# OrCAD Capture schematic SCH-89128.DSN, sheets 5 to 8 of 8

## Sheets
5 03 POWER: size D
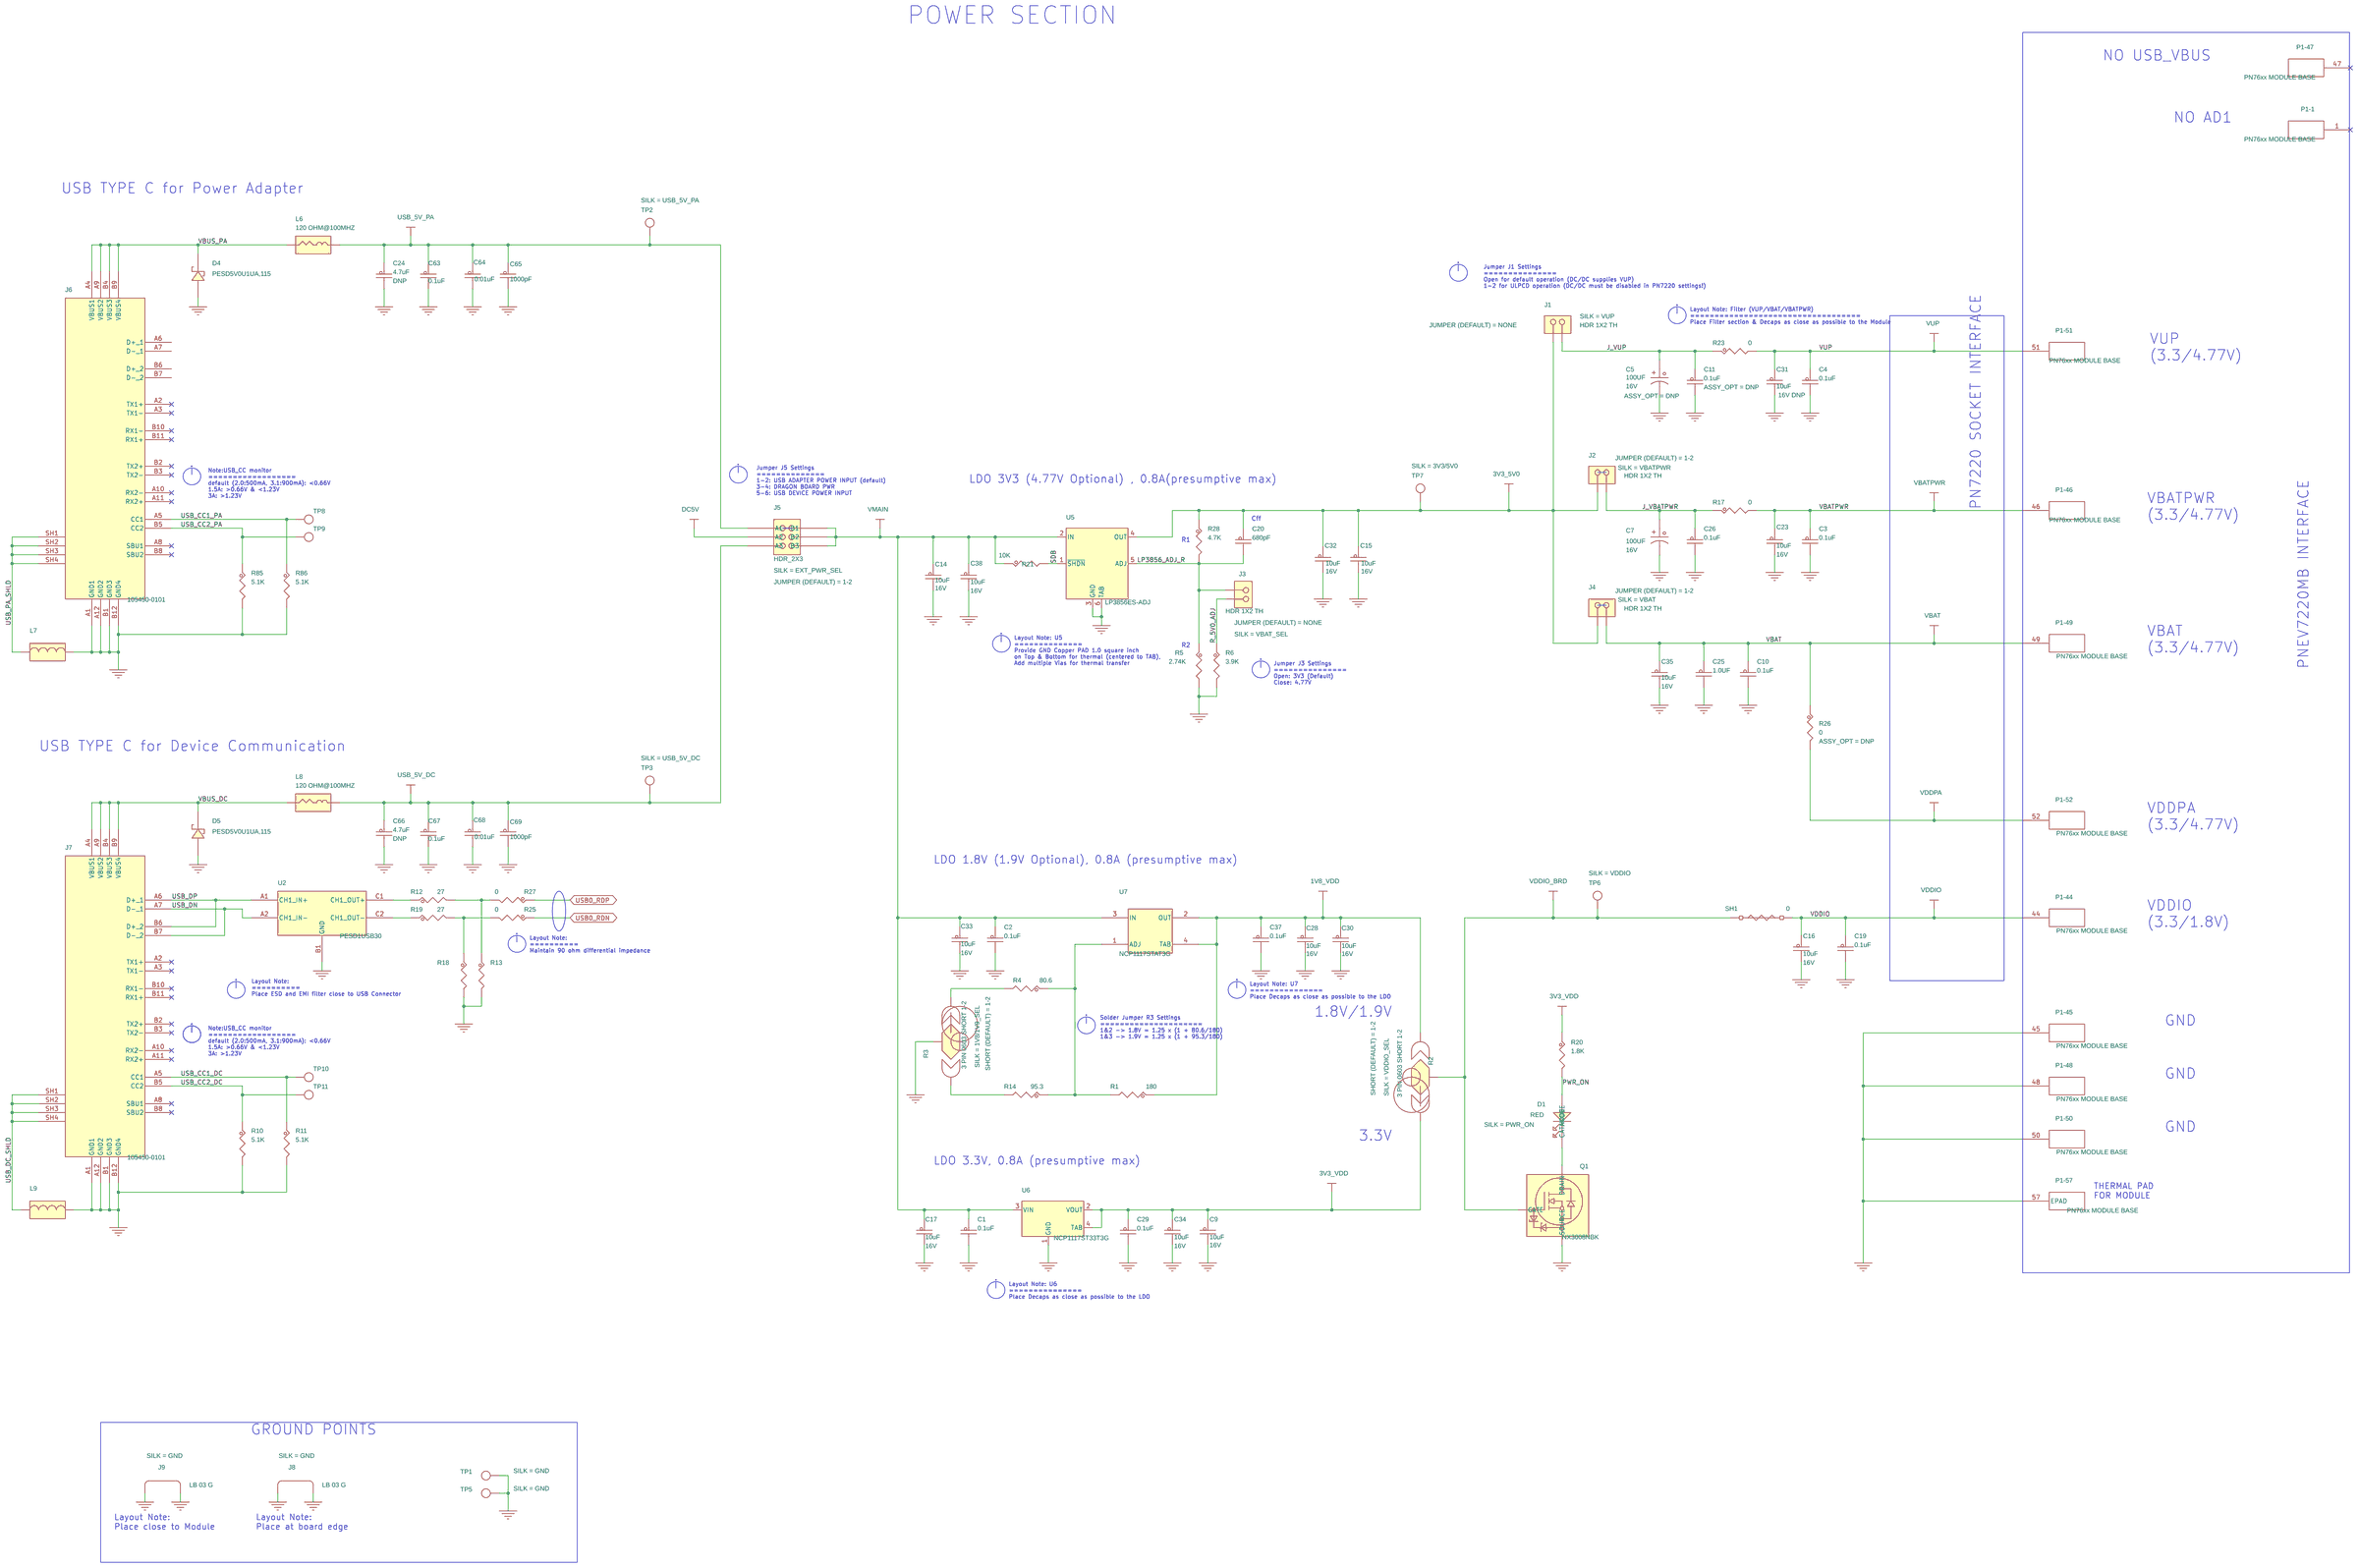
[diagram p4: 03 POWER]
6 04 NFCC Interface: size D
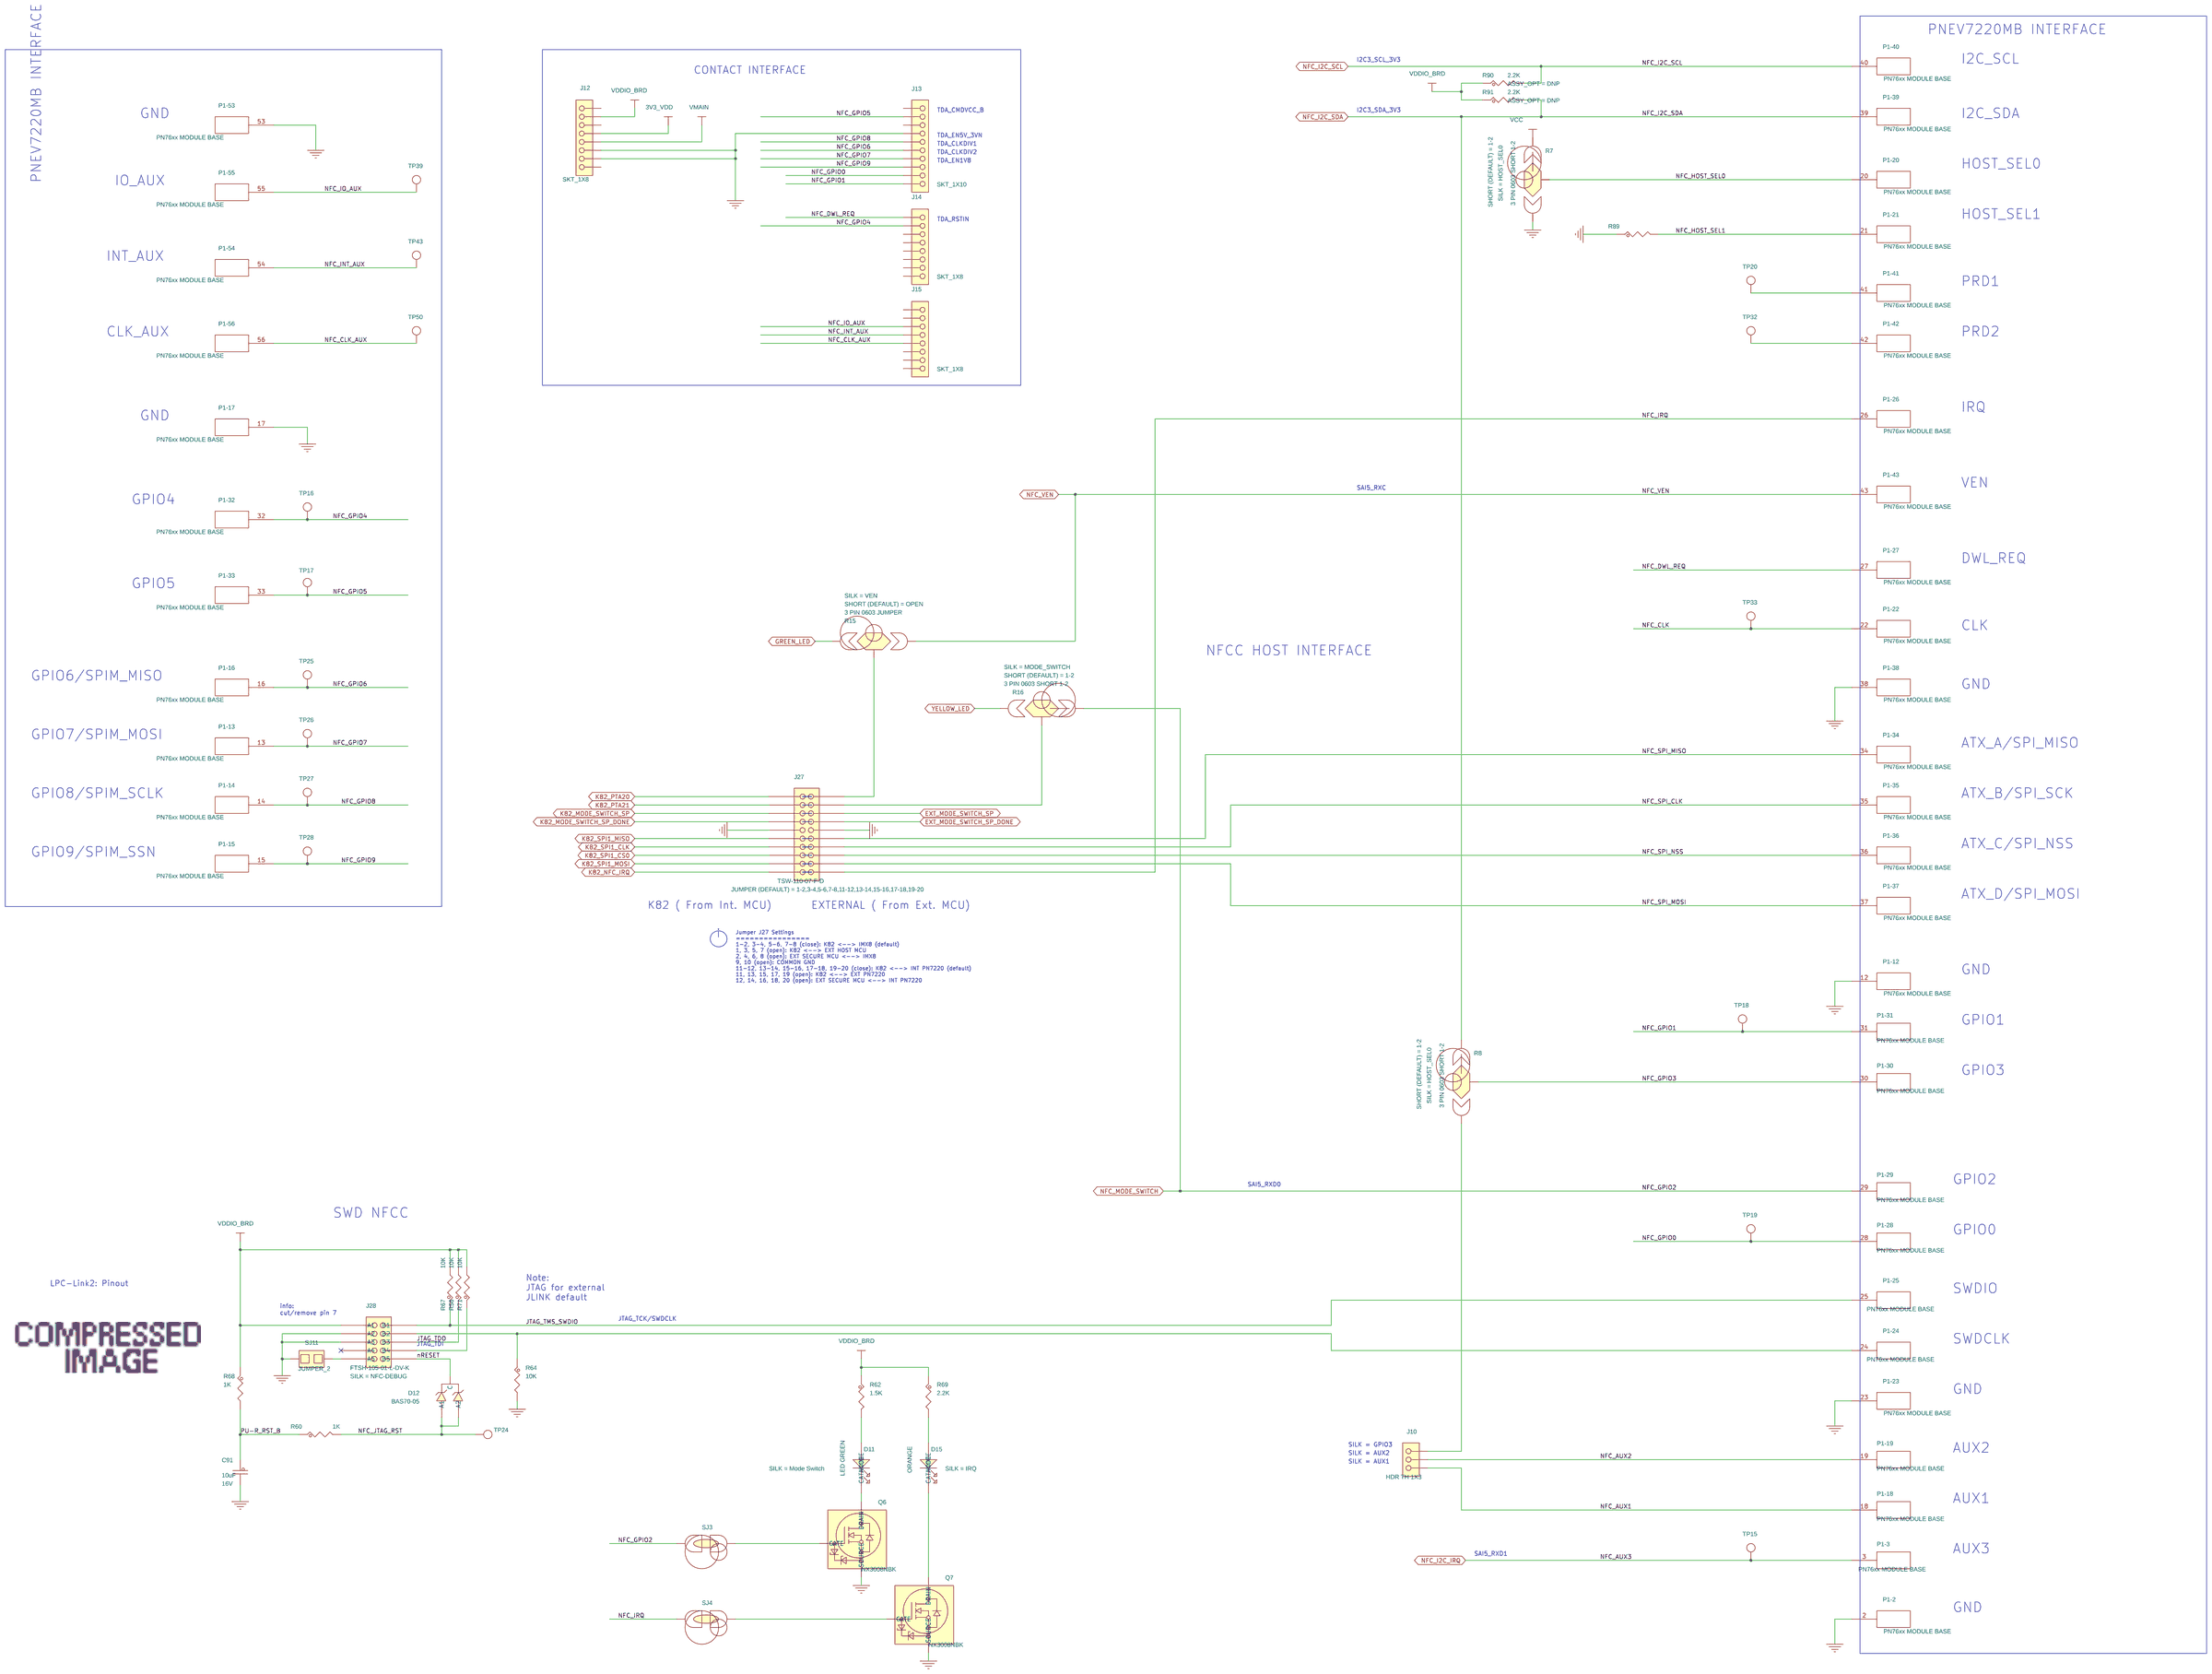
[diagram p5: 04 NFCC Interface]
7 05 NFC Antenna: size D
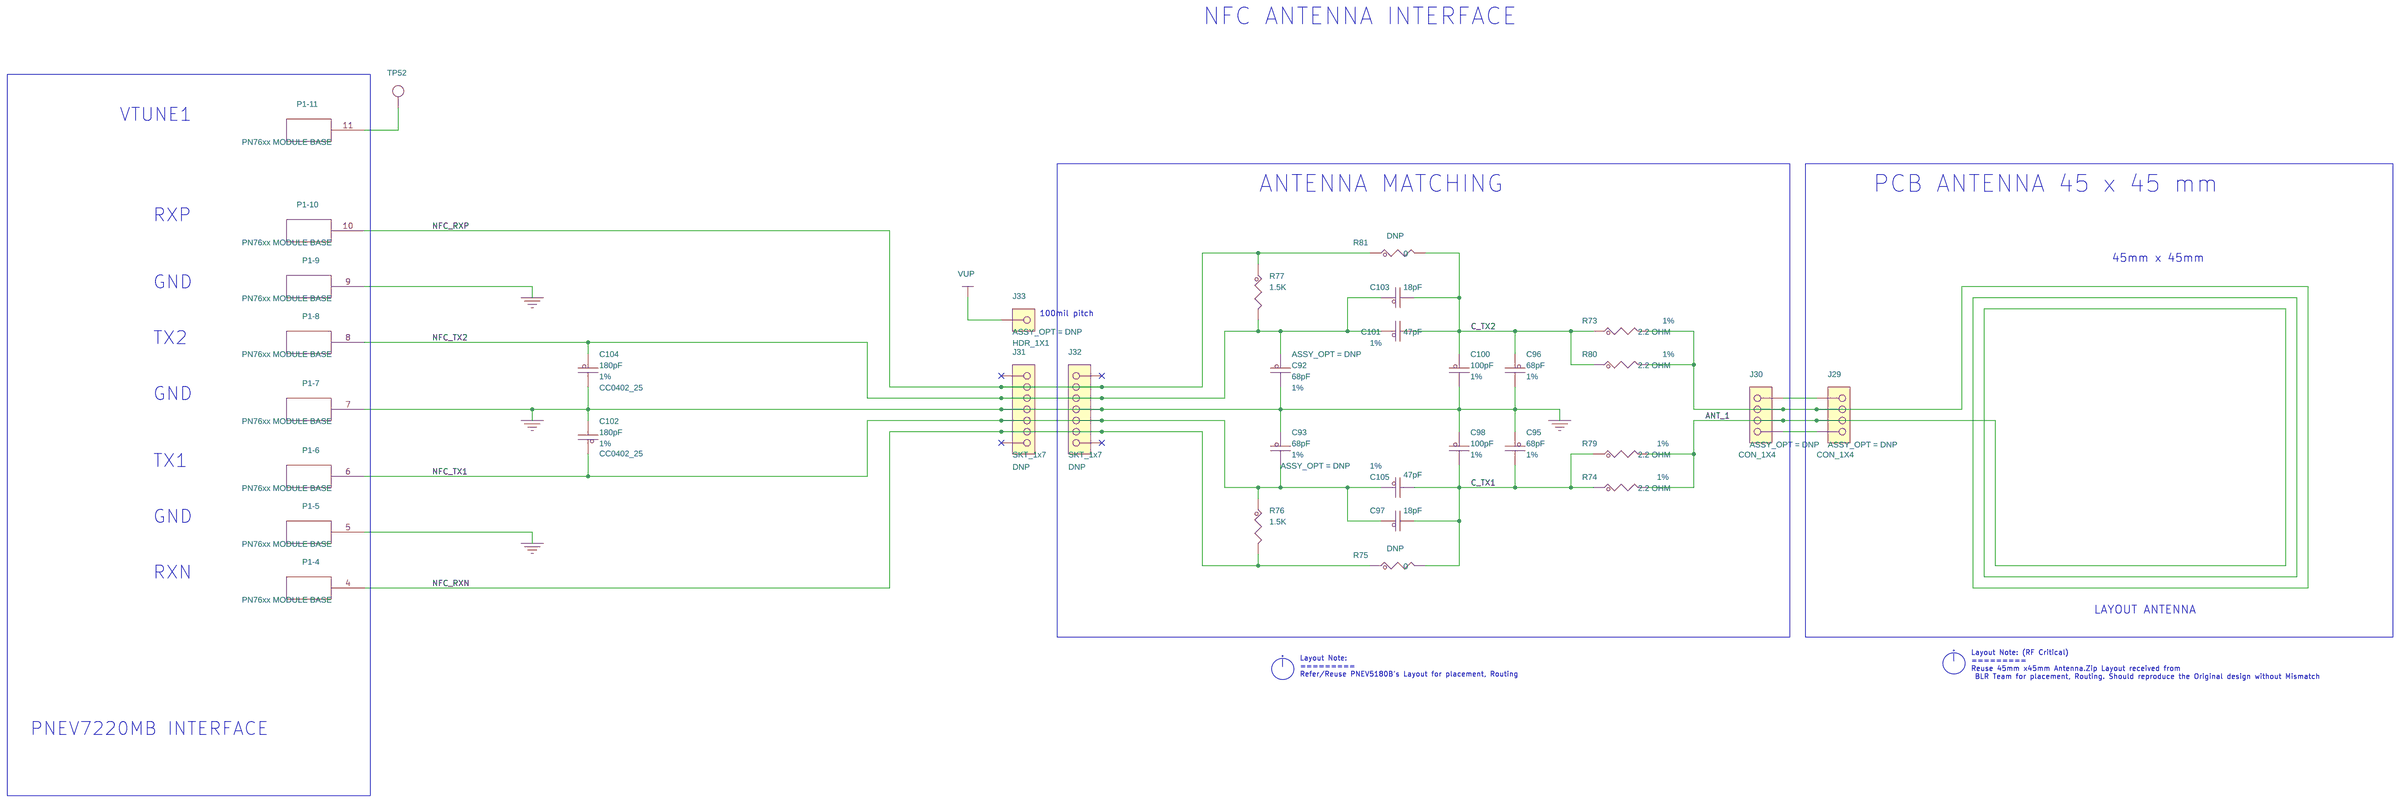
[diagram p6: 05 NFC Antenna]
8 06 IMX8 EVK: size D
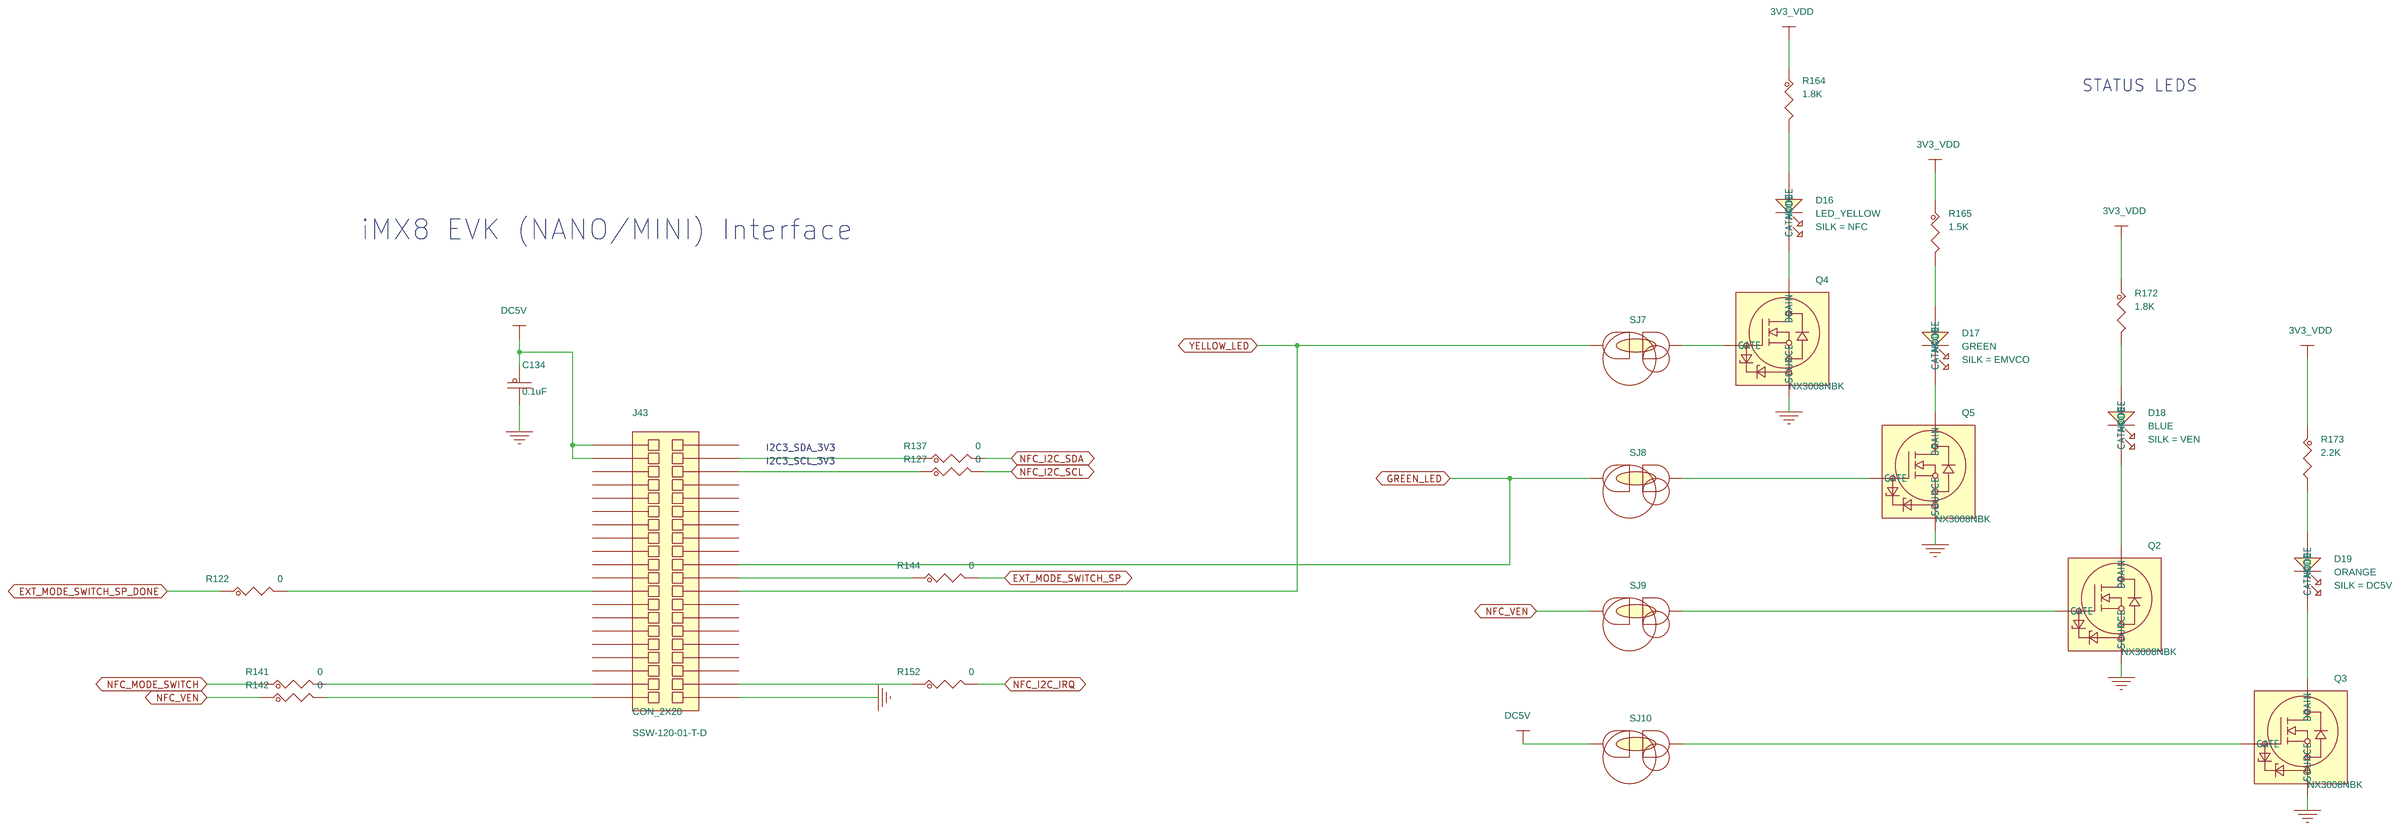
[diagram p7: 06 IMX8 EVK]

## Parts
sheet 03 POWER
C1  0.1uF  [CC0402_25]
C2  0.1uF  [CC0402_25]
C3  0.1uF  [CC0402_25]
C4  0.1uF  [CC0402_25]
C5  100UF  [CC7343]
C7  100UF  [CC7343]
C9  10uF  [CC0603_OV]
C10  0.1uF  [CC0402_25]
C11  0.1uF  [CC0402_25]
C14  10uF  [CC0603_OV]
C15  10uF  [CC0603_OV]
C16  10uF  [CC0603_OV]
C17  10uF  [CC0603_OV]
C19  0.1uF  [CC0402_25]
C20  680pF  [CC0603_OV]
C23  10uF  [CC0603_OV]
C24  4.7uF  [CC0603_OV]
C25  1.0UF  [0402_CC]
C26  0.1uF  [CC0402_25]
C28  10uF  [CC0603_OV]
C29  0.1uF  [CC0402_25]
C30  10uF  [CC0603_OV]
C31  10uF  [CC0603_OV]
C32  10uF  [CC0603_OV]
C33  10uF  [CC0603_OV]
C34  10uF  [CC0603_OV]
C35  10uF  [CC0603_OV]
C37  0.1uF  [CC0402_25]
C38  10uF  [CC0603_OV]
C63  0.1uF  [CC0402_25]
C64  0.01uF  [CC0402_25]
C65  1000pF  [CC0402_25]
C66  4.7uF  [CC0603_OV]
C67  0.1uF  [CC0402_25]
C68  0.01uF  [CC0402_25]
C69  1000pF  [CC0402_25]
D1  RED  [LED_0603]
D4  PESD5V0U1UA,115  [SOD-323-A]
D5  PESD5V0U1UA,115  [SOD-323-A]
J1  HDR 1X2 TH  [HDR_1X2]
J2  HDR 1X2 TH  [HDR_1X2]
J3  HDR 1X2 TH  [HDR_1X2]
J4  HDR 1X2 TH  [HDR_1X2]
J5  HDR_2X3  [HDR203]
J6  105450-0101  [con24_usb_typec_ra_smt]
J7  105450-0101  [con24_usb_typec_ra_smt]
J8  LB 03 G  [jump2_7p62_th]
J9  LB 03 G  [jump2_7p62_th]
L6  120 OHM@100MHZ  [IND_0603]
L7  330 OHM  [IND_0805]
L8  120 OHM@100MHZ  [IND_0603]
L9  330 OHM  [IND_0805]
Q1  NX3008NBK  [SOT23_A]
R1  180  [RC0402_25]
R2  3 PIN 0603 SHORT 1-2  [3pin_0603_solder_blob_jumper_short]
R3  3 PIN 0603 SHORT 1-2  [3pin_0603_solder_blob_jumper_short]
R4  80.6  [RC0402_25]
R5  2.74K  [RC0402_25]
R6  3.9K  [RC0603_OV]
R10  5.1K  [RC0603_OV]
R11  5.1K  [RC0603_OV]
R12  27  [RC0402_25]
R13  10K  [RC0402_25]
R14  95.3  [RC0402_25]
R17  0  [RC0603_OV]
R18  10K  [RC0402_25]
R19  27  [RC0402_25]
R20  1.8K  [RC0402_25]
R21  10K  [RC0402_25]
R23  0  [RC0603_OV]
R25  0  [RC0603_OV]
R26  0  [RC0603_OV]
R27  0  [RC0603_OV]
R28  4.7K  [RC0402_25]
R85  5.1K  [RC0603_OV]
R86  5.1K  [RC0603_OV]
SH1  0  [SH0603]
TP1  TEST POINT BLACK  [TEST_LOOP]
TP2  TEST POINT RED  [TEST_LOOP]
TP3  TEST POINT RED  [TEST_LOOP]
TP5  TEST POINT BLACK  [TEST_LOOP]
TP6  TEST POINT RED  [TEST_LOOP]
TP7  TEST POINT RED  [TEST_LOOP]
TP8  TPAD_030  [TPAD_030]
TP9  TPAD_030  [TPAD_030]
TP10  TPAD_030  [TPAD_030]
TP11  TPAD_030  [TPAD_030]
U2  PESD1USB30  [wlcsp5_0p4_0p82x1p22]
U5  LP3856ES-ADJ  [reg5_to263]
U6  NCP1117ST33T3G  [sot223]
U7  NCP1117STAT3G  [sot223]
sheet 04 NFCC Interface
C91  10uF  [CC0603_OV]
D11  LED GREEN  [LED_0603]
D12  BAS70-05  [SOT23_A]
D15  ORANGE  [LED_0603]
J10  HDR TH 1X3  [HDR103]
J12  SKT_1X8  [con_skt1x8_th]
J13  SKT_1X10  [con_skt1x10_th_104l]
J14  SKT_1X8  [con_skt1x8_th]
J15  SKT_1X8  [con_skt1x8_th]
J27  TSW-110-07-F-D  [hdr210]
J28  FTSH-105-01-L-DV-K  [hdr205_10m_50_sm_k]
Q6  NX3008NBK  [SOT23_A]
Q7  NX3008NBK  [SOT23_A]
R7  3 PIN 0603 SHORT 1-2  [3pin_0603_solder_blob_jumper_short]
R8  3 PIN 0603 SHORT 1-2  [3pin_0603_solder_blob_jumper_short]
R15  3 PIN 0603 JUMPER  [3pin_0603_solder_blob_jumper]
R16  3 PIN 0603 SHORT 1-2  [3pin_0603_solder_blob_jumper_short]
R56  10K  [RC0402_25]
R60  1K  [RC0402_25]
R62  1.5K  [RC0805_OV]
R64  10K  [RC0402_25]
R67  10K  [RC0402_25]
R68  1K  [RC0402_25]
R69  2.2K  [RC0402_25]
R71  10K  [RC0402_25]
R89  10K  [RC0402_25]
R90  2.2K  [RC0402_25]
R91  2.2K  [RC0402_25]
SJ3  0402 JUMPER  [0402_solder_blob_jumper_short]
SJ4  0402 JUMPER  [0402_solder_blob_jumper_short]
SJ11  JUMPER_2  [jump1x2_0805]
TP15  TPAD_040  [TPAD_040]
TP16  TPAD_040  [TPAD_040]
TP17  TPAD_040  [TPAD_040]
TP18  TPAD_040  [TPAD_040]
TP19  TPAD_040  [TPAD_040]
TP20  TPAD_040  [TPAD_040]
TP24  TPAD_040  [TPAD_040]
TP25  TPAD_040  [TPAD_040]
TP26  TPAD_040  [TPAD_040]
TP27  TPAD_040  [TPAD_040]
TP28  TPAD_040  [TPAD_040]
TP32  TPAD_040  [TPAD_040]
TP33  TPAD_040  [TPAD_040]
TP39  TPAD_040  [TPAD_040]
TP43  TPAD_040  [TPAD_040]
TP50  TPAD_040  [TPAD_040]
sheet 05 NFC Antenna
C92  68pF  [CC0805_OV]
C93  68pF  [CC0805_OV]
C95  68pF  [CC0805_OV]
C96  68pF  [CC0805_OV]
C97  18pF  [CC0805_OV]
C98  100pF  [CC0805_OV]
C100  100pF  [CC0805_OV]
C101  47pF  [CC0805_OV]
C102  180pF  [CC0402_25]
C103  18pF  [CC0805_OV]
C104  180pF  [CC0402_25]
C105  47pF  [CC0805_OV]
J29  CON_1X4  [con_skt1x4_th]
J30  CON_1X4  [con_skt1x4_th]
J31  SKT_1x7  [con_1x7_skt_2p54_th]
J32  SKT_1x7  [con_1x7_skt_2p54_th]
J33  HDR_1X1  [HDR_1X1]
P1  PN76xx MODULE BASE  [module56_1p52_23x23mm]  (sections -1,-10,-11,-12,-13,-14,-15,-16,-17,-18,-19,-2,-20,-21,-22,-23,-24,-25,-26,-27,-28,-29,-3,-30,-31,-32,-33,-34,-35,-36,-37,-38,-39,-4,-40,-41,-42,-43,-44,-45,-46,-47,-48,-49,-5,-50,-51,-52,-53,-54,-55,-56,-57,-6,-7,-8,-9)
R73  2.2 OHM  [RC0805_OV]
R74  2.2 OHM  [RC0805_OV]
R75  0  [RC0805_OV]
R76  1.5K  [RC0805_OV]
R77  1.5K  [RC0805_OV]
R79  2.2 OHM  [RC0805_OV]
R80  2.2 OHM  [RC0805_OV]
R81  0  [RC0805_OV]
TP52  TPAD_040  [TPAD_040]
sheet 06 IMX8 EVK
C134  0.1uF  [CC0402_25]
D16  LED_YELLOW  [LED_0603]
D17  GREEN  [LED_0603]
D18  BLUE  [LED_0603]
D19  ORANGE  [LED_0603]
J43  CON_2X20  [con_skt2x20_th]
Q2  NX3008NBK  [SOT23_A]
Q3  NX3008NBK  [SOT23_A]
Q4  NX3008NBK  [SOT23_A]
Q5  NX3008NBK  [SOT23_A]
R122  0  [RC0603_OV]
R127  0  [RC0603_OV]
R137  0  [RC0603_OV]
R141  0  [RC0603_OV]
R142  0  [RC0603_OV]
R144  0  [RC0603_OV]
R152  0  [RC0603_OV]
R164  1.8K  [RC0402_25]
R165  1.5K  [RC0805_OV]
R172  1.8K  [RC0402_25]
R173  2.2K  [RC0402_25]
SJ7  0402 JUMPER  [0402_solder_blob_jumper_short]
SJ8  0402 JUMPER  [0402_solder_blob_jumper_short]
SJ9  0402 JUMPER  [0402_solder_blob_jumper_short]
SJ10  0402 JUMPER  [0402_solder_blob_jumper_short]

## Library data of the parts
C1-C4 C10 C19 C26 C29 C37 C63 C67 = CAP_NP: CAP CER 0.1UF 16V 10% X5R 0402; AGILE_PN: 150-75663; CAD_APPROVED: Yes; FPLIST: CC0402_25,CC0402_HD,0402_CC,CC0402_18,capc0402_l; HEIGHT: 1; MFG_NAME01: MURATA; MFG_PN01: GRM155R61C104KA88D; PRIORITY_PN: 021-00169; Package Size: 1x0.5MM; Package Type: SMT; ROHS: NULL; Rated Voltage: 16V; Temp Range: -55C to +85C; Tolerance: 10%; VOLTAGE: 16V
C5 = CAP_POL: CAP TANT ESR=0.1 OHM 100UF 16V 10% -- 7343-43; 3D_Mechanical_Footprint_File: http://fcl.am.freescale.net/ALLEGRO/step/cc7343.step; AGILE_PN: 150-75159; ASSY_OPT: DNP; CAD_APPROVED: YES; HEIGHT: 4.3; MFG_NAME01: AVX; MFG_PN01: TPSE107K016R0100; Package Size: 7343-43; Package Type: 7; ROHS: Yes; Rated Voltage: 16V; Tolerance: 10%; VOLTAGE: 16V
C7 = CAP_POL: CAP TANT ESR=0.1 OHM 100UF 16V 10% -- 7343-43; 3D_Mechanical_Footprint_File: http://fcl.am.freescale.net/ALLEGRO/step/cc7343.step; AGILE_PN: 150-75159; CAD_APPROVED: YES; HEIGHT: 4.3; MFG_NAME01: AVX; MFG_PN01: TPSE107K016R0100; Package Size: 7343-43; Package Type: 7; ROHS: Yes; Rated Voltage: 16V; Tolerance: 10%; VOLTAGE: 16V
C9 C14-C17 C28 C30 C32-C35 C38 = CAP_NP: CAP CER 10.0uF 16V 10% X5R 0603; AGILE_PN: 150-80060; CAD_APPROVED: Yes; FPLIST: CC0603_OV,CC0603,0603_CC,cc0603_0805_nsp; HEIGHT: 0.9; MFG_NAME01: MURATA; MFG_PN01: GRM188R61C106KAALD; Package Size: 0603; Package Type: SMT; ROHS: Yes; Rated Voltage: 16V; TOL: 10%; Temp Range: -55C to +85C; Temp_Range: -55°C to +85°C; Tolerance: 10%; VOLTAGE: 16V
C11 = CAP_NP: CAP CER 0.1UF 16V 10% X5R 0402; AGILE_PN: 150-75663; ASSY_OPT: DNP; CAD_APPROVED: Yes; FPLIST: CC0402_25,CC0402_HD,0402_CC,CC0402_18,capc0402_l; HEIGHT: 1; MFG_NAME01: MURATA; MFG_PN01: GRM155R61C104KA88D; PRIORITY_PN: 021-00169; Package Size: 1x0.5MM; Package Type: SMT; ROHS: NULL; Rated Voltage: 16V; Temp Range: -55C to +85C; Tolerance: 10%; VOLTAGE: 16V
C20 = CAP_NP: CAP CER 680PF 50V 10% X7R 0603; AGILE_PN: 150-79887; CAD_APPROVED: Yes; FPLIST: CC0603_OV,CC0603,0603_CC; HEIGHT: 0.87; MFG_NAME01: KEMET; MFG_PN01: C0603C681K5RACTU; Package Size: 0603; Package Type: tape & reel; ROHS: NULL; Rated Voltage: 50V; Temp Range: -55C to +125C; Temp_Range: -55C to +125C; Tolerance: 10%; VOLTAGE: 50V
C23 C91 = CAP_NP: CAP CER 10.0uF 16V 10% X5R 0603; AGILE_PN: 150-80060; CAD_APPROVED: Yes; FPLIST: CC0603_OV,CC0603,0603_CC,cc0603_0805_nsp; HEIGHT: 0.9; MFG_NAME01: MURATA; MFG_PN01: GRM188R61C106KAALD; Package Size: 0603; Package Type: SMT; ROHS: Yes; Rated Voltage: 16V; Temp Range: -55C to +85C; Temp_Range: -55°C to +85°C; Tolerance: 10%; VOLTAGE: 16V
C24 C66 = CAP_NP: CAP CER 4.7uF 16V 10% X5R 0603; AGILE_PN: 150-80061; ASSY_OPT: DNP; CAD_APPROVED: Yes; HEIGHT: 0.95; MFG_NAME01: MURATA; MFG_PN01: GRM188R61C475KE11D; ROHS: Yes; Rated Voltage: 16V; Temp Range: -55C to +85C; Tolerance: 10%; VOLTAGE: 16V
C25 = CAP_NP: CAP CER 1.0UF 10V 10% X5R 0402; AGILE_PN: 150-75772; CAD_APPROVED: Yes; FPLIST: CC0402_25,CC0402_HD,0402_CC; HEIGHT: 0.6; MFG_NAME01: YAGEO AMERICA; MFG_PN01: CC0402KRX5R6BB105; Package Size: 0402; ROHS: Yes; Rated Voltage: 10V; Temp Range: -55C to +85C; Tolerance: 10%; VOLTAGE: 10V; voltage rating: 10V
C31 = CAP_NP: CAP CER 10.0uF 16V 10% X5R 0603; AGILE_PN: 150-80060; ASSY_OPT: DNP; CAD_APPROVED: Yes; FPLIST: CC0603_OV,CC0603,0603_CC,cc0603_0805_nsp; HEIGHT: 0.9; MFG_NAME01: MURATA; MFG_PN01: GRM188R61C106KAALD; Package Size: 0603; Package Type: SMT; ROHS: Yes; Rated Voltage: 16V; Temp Range: -55C to +85C; Temp_Range: -55°C to +85°C; Tolerance: 10%; VOLTAGE: 16V
C64 C68 = CAP_NP: CAP CER 0.01UF 25V 10% X7R 0402; AGILE_PN: 150-75183; CAD_APPROVED: Yes; FPLIST: CC0402_25,CC0402_HD,0402_CC; HEIGHT: 0.635; MFG_NAME01: AVX; MFG_PN01: 04023C103KAT2A; ROHS: Yes; Rated Voltage: 25V; Temp Range: -55C to +125C; Tolerance: 10%; VOLTAGE: 25V
C65 C69 = CAP_NP: CAP CER 1000pF 50V 10% X7R AEC-Q200 0402; AGILE_PN: 150-79040; CAD_APPROVED: Yes; FPLIST: CC0402_25,CC0402_HD,0402_CC; HEIGHT: 0.55; MFG_NAME01: MURATA; MFG_PN01: GCM155R71H102KA37D; Package Size: 0402; Package Type: Paper Tape; ROHS: Yes; Rated Voltage: 50V; Temp Range: -55C to +125C; Tolerance: 10%; VOLTAGE: 50V
D1 = LED: LED ULTRA BRIGHT RED SGL 30MA 0603; AGILE_PN: 370-75079; CAD_APPROVED: Yes; HEIGHT: 0.9; MFG_NAME01: LITE ON; MFG_PN01: LTST-C190KRKT; ROHS: Yes; Rated Voltage: 2V; SILK: PWR_ON; Temp Range: -30° C to + 85° C; VOLTAGE: 2V
D4 D5 = DIODE_SCHTKY: DIODE ZENER ESD UNIDIR 5V AEC-Q101 SOD323; AGILE_PN: 480-80104; CAD_APPROVED: Yes; HEIGHT: 1.1; MFG_NAME01: NEXPERIA; Rated Voltage: 5V; VOLTAGE: 5V
J1 = CONN_HDR_2X1: HDR 1X2 TH 100MIL SP 339H AU 98L; 3D_Mechanical_Footprint_File: http://fcl.am.freescale.net/ALLEGRO/step/hdr102_338h.STEP; AGILE_PN: 210-75439; CAD_APPROVED: YES; FPLIST: HDR102,SH_HDR102_BOTTOM; HEIGHT: 8.71; JUMPER (DEFAULT): NONE; MFG_NAME01: SAMTEC; MFG_PN01: TSW-102-07-G-S; ROHS: NULL; SILK: VUP; Temp Range: -55°C to +125°C
J2 = CONN_HDR_2X1: HDR 1X2 TH 100MIL SP 339H AU 98L; 3D_Mechanical_Footprint_File: http://fcl.am.freescale.net/ALLEGRO/step/hdr102_338h.STEP; AGILE_PN: 210-75439; CAD_APPROVED: YES; FPLIST: HDR102,SH_HDR102_BOTTOM; HEIGHT: 8.71; JUMPER (DEFAULT): 1-2; MFG_NAME01: SAMTEC; MFG_PN01: TSW-102-07-G-S; ROHS: NULL; SILK: VBATPWR; Temp Range: -55°C to +125°C
J3 = CONN_HDR_2X1: HDR 1X2 TH 100MIL SP 339H AU 98L; 3D_Mechanical_Footprint_File: http://fcl.am.freescale.net/ALLEGRO/step/hdr102_338h.STEP; AGILE_PN: 210-75439; CAD_APPROVED: YES; FPLIST: HDR102,SH_HDR102_BOTTOM; HEIGHT: 8.71; JUMPER (DEFAULT): NONE; MFG_NAME01: SAMTEC; MFG_PN01: TSW-102-07-G-S; ROHS: NULL; SILK: VBAT_SEL; Temp Range: -55°C to +125°C
J4 = CONN_HDR_2X1: HDR 1X2 TH 100MIL SP 339H AU 98L; 3D_Mechanical_Footprint_File: http://fcl.am.freescale.net/ALLEGRO/step/hdr102_338h.STEP; AGILE_PN: 210-75439; CAD_APPROVED: YES; FPLIST: HDR102,SH_HDR102_BOTTOM; HEIGHT: 8.71; JUMPER (DEFAULT): 1-2; MFG_NAME01: SAMTEC; MFG_PN01: TSW-102-07-G-S; ROHS: NULL; SILK: VBAT; Temp Range: -55°C to +125°C
J5 = CONN_HDR_3X2: HDR 2X3 TH 100MIL CTR 338H AU 100L; 3D_Mechanical_Footprint_File: http://fcl.am.freescale.net/ALLEGRO/step/hdr203.STEP; AGILE_PN: 210-81057; CAD_APPROVED: Yes; HEIGHT: 8.59; JUMPER (DEFAULT): 1-2; MFG_NAME01: SAMTEC; MFG_PN01: TSW-103-07-F-D; ROHS: Yes; SILK: EXT_PWR_SEL; Temp Range: -55°C to +125°C
J6 J7 = USB24_TYPEC_105450: CON 24 USB TYPE C  0.5MM RA SHLD SKT SP 134H AU; 3D_Mechanical_Footprint_File: http://fcl.am.freescale.net/ALLEGRO/step/con24_usb_typec_ra_smt.step; AGILE_PN: 211-80150; CAD_APPROVED: Yes; HEIGHT: 3.41; MFG_NAME01: MOLEX; ROHS: Yes
J8 J9 = JUMPER1X2_TH: CON 1X2 JUMPER TH 7.62MM 79H AU 276L; 3D_Mechanical_Footprint_File: http://fcl.am.freescale.net/ALLEGRO/step/jump2_7p62_th.STEP; AGILE_PN: 210-81045; CAD_APPROVED: Yes; HEIGHT: 2; MFG_NAME01: FISCHER ELECTRONIC; ROHS: Yes; SILK: GND
L6 L8 = BLM18R: IND FER BEAD 120 OHM@100MHZ 3A 25% 0603; AGILE_PN: 180-77625; CAD_APPROVED: Yes; HEIGHT: 0.65; MFG_NAME01: MURATA; MFG_PN01: BLM18SG121TN1D; Package Size: 0603; ROHS: Yes
L7 L9 = BEAD: IND FER BEAD 330OHM@100MHZ 2.5A -- SMT; 3D_Mechanical_Footprint_File: http://fcl.am.freescale.net/ALLEGRO/step/ind_0805.STEP; AGILE_PN: 180-30021; CAD_APPROVED: YES; HEIGHT: 1.05; MFG_NAME01: TDK; MFG_PN01: MPZ2012S331AT000; PART_TYPE: FERRITE; ROHS: Yes; TOL: 25%; Temp Range: -55°C to +125°C; Tolerance: 25%
Q1-Q7 = NMOS_NX3008NBK: TRAN NMOS PWR 30V 400mA AEC-Q101 SOT23; AGILE_PN: 480-79305; CAD_APPROVED: Yes; FPLIST: SOT23_A,TO-236; HEIGHT: 1.1; MFG_NAME01: NEXPERIA; MFG_PN01: NX3008NBK,215; ROHS: Yes
R1 = RES: RES MF 180 OHM 1/16W 1% 0402; AGILE_PN: 470-30765; CAD_APPROVED: Yes; FPLIST: RC0402_25,RC0402_HD,0402_CC; HEIGHT: 0.40; MFG_NAME01: WALSIN TECHNOLOGY CORP.; MFG_PN01: WR04X1800FTL; ROHS: Yes; Tolerance: 1%
R2 = 3_Pad_Solder_Blob_Jumper_short: SOLDER BLOB JUMPER 3PIN 1-2 SHORT 0603 - NO PART TO ORDER; AGILE_PN: 470-83437; CAD_APPROVED: Yes; HEIGHT: 0.1016; ROHS: Yes; SHORT (DEFAULT): 1-2; SILK: VDDIO_SEL
R3 = 3_Pad_Solder_Blob_Jumper_short: SOLDER BLOB JUMPER 3PIN 1-2 SHORT 0603 - NO PART TO ORDER; AGILE_PN: 470-83437; CAD_APPROVED: Yes; HEIGHT: 0.1016; ROHS: Yes; SHORT (DEFAULT): 1-2; SILK: 1V8/1V9_SEL
R4 = RES: RES MF 80.6 OHM 1/10W 1% AEC-Q200 0402; AGILE_PN: 470-30732; CAD_APPROVED: Yes; FPLIST: RC0402_25,RC0402_HD,0402_CC; HEIGHT: 0.40; MFG_NAME01: KOA SPEER; MFG_PN01: RK73H1ETTP80R6F; ROHS: Yes; Temp Range: -55C to +155C; Tolerance: 1%
R5 = RES: RES MF 2.74K 1/16W 1% AEC-Q200 0402; AGILE_PN: 470-30882; CAD_APPROVED: Yes; FPLIST: RC0402_25,RC0402_HD,0402_CC; HEIGHT: 0.40; MFG_NAME01: VISHAY INTERTECHNOLOGY; MFG_PN01: CRCW04022K74FK; ROHS: Yes; Temp Range: –55 °C to +155 °C; Tolerance: 1%
R6 = RES: RES MF 3.9K 1/10W 1% 0603; AGILE_PN: 470-81459; CAD_APPROVED: Yes; FPLIST: RC0603_OV,RC0603,0603_CC; HEIGHT: 0.5; MFG_NAME01: YAGEO AMERICA; MFG_PN01: RC0603FR-073K9L; ROHS: Yes; Temp Range: -55C to +155C; Tolerance: 1%
R10 R11 R85 R86 = RES: RES MF 5.1K 1/10W 1% 0603; AGILE_PN: 470-80925; CAD_APPROVED: Yes; HEIGHT: 0.55; MFG_NAME01: YAGEO AMERICA; MFG_PN01: RC0603FR-075K1L; ROHS: Yes; Tolerance: 1%
R12 R19 = RES: RES MF 27OHM 1/16W 5% 0402; AGILE_PN: 470-75611; CAD_APPROVED: Yes; HEIGHT: 0.45; MFG_NAME01: BOURNS; MFG_PN01: CR0402-JW-270GLF; ROHS: Yes; Tolerance: 5%; VOLTAGE: 1/16W
R13 R18 R89 = RES: RES MF 10K 1/16W 1% 0402; AGILE_PN: 470-80452; CAD_APPROVED: Yes; FPLIST: RC0402_25,RC0402_HD,0402_CC,RC0402_X2; HEIGHT: 0.40; MFG_NAME01: VISHAY; MFG_PN01: CRCW040210K0FKEDC; ROHS: Yes; TOL: 5%; Tolerance: 1%
R14 = RES: RES MF 95.3 OHM 1/10W 1% AEC-Q200 0402; AGILE_PN: 470-30741; CAD_APPROVED: Yes; FPLIST: RC0402_25,RC0402_HD,0402_CC; HEIGHT: 0.40; MFG_NAME01: KOA SPEER; MFG_PN01: RK73H1ETTP95R3F; ROHS: Yes; Temp Range: -55C to +155C; Tolerance: 1%
R17 R23 = RES: RES MF ZERO OHM 1/10W -- 0603; AGILE_PN: 470-80866; CAD_APPROVED: Yes; FPLIST: RC0603_OV,RC0603,R603-X2,r603-x2_b,0603_CC,IND_0603HP_NSP,CC0603_OV_NSP; HEIGHT: 0.6; MFG_NAME01: VISHAY; MFG_PN01: CRCW06030000Z0EAC; ROHS: NULL; Temp Range: –55 °C to +155 °C
R20 R164 R172 = RES: RES MF 1.8K 1/16W 5% 0402; AGILE_PN: 470-75640; CAD_APPROVED: Yes; FPLIST: RC0402_25,RC0402_HD,0402_CC; HEIGHT: 0.4; MFG_NAME01: BOURNS; MFG_PN01: CR0402-JW-182GLF; ROHS: Yes; Tolerance: 5%
R21 = RES: RES MF 10K 1/16W 1% 0402; AGILE_PN: 470-80452; CAD_APPROVED: Yes; FPLIST: RC0402_25,RC0402_HD,0402_CC; HEIGHT: 0.40; MFG_NAME01: VISHAY; MFG_PN01: CRCW040210K0FKEDC; ROHS: Yes; Temp Coefficient - ppm/K: ±100 ppm/°C; Tolerance: 1%
R25 R27 R122 R127 R137 R141 R142 R144 R152 = RES: RES MF ZERO OHM 1/10W -- 0603; AGILE_PN: 470-80866; CAD_APPROVED: Yes; FPLIST: RC0603_OV,RC0603,R603-X2,0603_CC; HEIGHT: 0.6; MFG_NAME01: VISHAY; MFG_PN01: CRCW06030000Z0EAC; ROHS: NULL; TOL: 1%; Temp Range: –55 °C to +155 °C
R26 = RES: RES MF ZERO OHM 1/10W -- 0603; AGILE_PN: 470-80866; ASSY_OPT: DNP; CAD_APPROVED: Yes; FPLIST: RC0603_OV,RC0603,R603-X2,r603-x2_b,0603_CC,IND_0603HP_NSP,CC0603_OV_NSP; HEIGHT: 0.6; MFG_NAME01: VISHAY; MFG_PN01: CRCW06030000Z0EAC; ROHS: NULL; Temp Range: –55 °C to +155 °C
R28 = RES: RES MF 4.70K 1/16W 1% 0402; AGILE_PN: 470-75418; CAD_APPROVED: Yes; FPLIST: RC0402_25,RC0402_HD,0402_CC; HEIGHT: 0.4; MFG_NAME01: WALSIN TECHNOLOGY CORP.; MFG_PN01: WR04X4701FTL; ROHS: Yes; Tolerance: 1%; VOLTAGE: 1/16W
SH1 = RES_SHORT-2: ZERO OHM CUT TRACE 0603 PADS; NO PART TO ORDER; AGILE_PN: 470-80018; CAD_APPROVED: Yes; FPLIST: SH0603,SH0603_CC,SH0603-X2_PIN1TO2,SH0603-X2_PIN2TO3; HEIGHT: 0.1; ROHS: NULL
TP1 TP5 = TESTLOOP: TEST POINT BLACK 40 MIL DRILL 180 MIL TH 109L; 3D_Mechanical_Footprint_File: http://fcl.am.freescale.net/ALLEGRO/step/test_loop.STEP; AGILE_PN: 210-75683; CAD_APPROVED: Yes; HEIGHT: 4.8; MFG_NAME01: KEYSTONE ELECTRONICS; MFG_PN01: 5001; ROHS: NULL; SILK: GND
TP2 = TESTLOOP: TEST POINT RED 40 MIL DRILL 180 MIL TH 109L; AGILE_PN: 210-75684; CAD_APPROVED: Yes; HEIGHT: 4.8; MFG_NAME01: KEYSTONE ELECTRONICS; MFG_PN01: 5000; ROHS: Yes; SILK: USB_5V_PA; Temp Range: -50°C to +146°C
TP3 = TESTLOOP: TEST POINT RED 40 MIL DRILL 180 MIL TH 109L; AGILE_PN: 210-75684; CAD_APPROVED: Yes; HEIGHT: 4.8; MFG_NAME01: KEYSTONE ELECTRONICS; MFG_PN01: 5000; ROHS: Yes; SILK: USB_5V_DC; Temp Range: -50°C to +146°C
TP6 = TESTLOOP: TEST POINT RED 40 MIL DRILL 180 MIL TH 109L; AGILE_PN: 210-75684; CAD_APPROVED: Yes; HEIGHT: 4.8; MFG_NAME01: KEYSTONE ELECTRONICS; MFG_PN01: 5000; ROHS: Yes; SILK: VDDIO; Temp Range: -50°C to +146°C
TP7 = TESTLOOP: TEST POINT RED 40 MIL DRILL 180 MIL TH 109L; AGILE_PN: 210-75684; CAD_APPROVED: Yes; HEIGHT: 4.8; MFG_NAME01: KEYSTONE ELECTRONICS; MFG_PN01: 5000; ROHS: Yes; SILK: 3V3/5V0; Temp Range: -50°C to +146°C
TP8-TP11 = TESTLOOP: TEST POINT PAD 30MIL DIA SMT, NO PART TO ORDER; 3D_Mechanical_Footprint_File: http://fcl.am.freescale.net/ALLEGRO/step/tpad_030.STEP; AGILE_PN: 211-76642; CAD_APPROVED: Yes; HEIGHT: 0.1; MFG_NAME01: NOTACOMPONENT; MFG_PN01: NOTACOMPONENT; ROHS: Yes
U2 = PESD1USB30: DIODE ESD USB 5V WLCSP5; 3D_Mechanical_Footprint_File: http://fcl.am.freescale.net/ALLEGRO/step/wlcsp5_0p4_0p82x1p22.STEP; AGILE_PN: 315-81117; CAD_APPROVED: Yes; HEIGHT: 0.6; MFG_NAME01: NEXPERIA; ROHS: Yes; VOLTAGE: 5V
U5 = LT1963A_DDPAK_6P: IC VREG LDO ADJ 3A 2.5-7V TO-263-5; 3D_Mechanical_Footprint_File: http://fcl.am.freescale.net/ALLEGRO/step/reg5_to263.STEP; AGILE_PN: 315-81634; CAD_APPROVED: Yes; HEIGHT: 4.65; MFG_NAME01: TEXAS INSTRUMENTS; MFG_PN01: LP3856ES-ADJ/NOPB; ROHS: Yes; Temp Range: -40C to +125C; Temp_Range: -40C to +125C; VOLTAGE: 2.5-7V
U6 = LD1117AS18: IC VREG LDO 1A 3.3V SOT223; AGILE_PN: 312-80039; CAD_APPROVED: Yes; HEIGHT: 1.8; MFG_NAME01: ON SEMICONDUCTOR; ROHS: Yes; Temp Range: 0°C to +125°C; VOLTAGE: 3.3V
U7 = NCP1117: IC VREG ADJ 1A 20.0V SOT-223; AGILE_PN: 315-30070; CAD_APPROVED: Yes; HEIGHT: 1.8; MFG_NAME01: ON SEMICONDUCTOR; ROHS: Yes; VOLTAGE: 20V
D11 = LED: LED GRN SGL 20MA 0603; AGILE_PN: 370-76565; CAD_APPROVED: Yes; HEIGHT: 0.67; MFG_NAME01: OSRAM; MFG_PN01: LG L29K-G2J1-24-Z; ROHS: Yes; Rated Voltage: 1.7V; SILK: Mode Switch
D12 = DIODE_DUAL_SCH_3P: DIODE SCH DUAL 70mA 410mV AEC-Q101 SOT23; AGILE_PN: 480-79750; CAD_APPROVED: Yes; HEIGHT: 1.1; MFG_NAME01: NEXPERIA; MFG_PN01: BAS70-05,215; REQUESTED_COMPLETION_DATE: Not an expedite request; ROHS: Yes; Rated Voltage: 0.41V; Temp Range: -65C to +150C; Temp_Range: -65C to +150C; VOLTAGE: 0.41V
D15 = LED: LED ULTRA BRIGHT ORANGE 20MA 2V SMT 0603; AGILE_PN: 370-75080; CAD_APPROVED: Yes; HEIGHT: 0.8; MFG_NAME01: LITE ON; MFG_PN01: LTST-C190KFKT; ROHS: Yes; SILK: IRQ
J10 = CONN_HDR_3X1: HDR 1X3 TH 100MIL SP 339H AU 100L; 3D_Mechanical_Footprint_File: http://fcl.am.freescale.net/ALLEGRO/step/hdr103.STEP; AGILE_PN: 210-75726; CAD_APPROVED: Yes; HEIGHT: 8.65; MFG_NAME01: SAMTEC; MFG_PN01: TSW-103-07-G-S; Package Size: 7.62 x 2.54 mm; ROHS: NULL; Temp Range: -55°C to +125°C
J12 J14 J15 = CONN_HDR_8X1: CON 1X8 SKT TH 100MIL CTR 340H AU 104L; 3D_Mechanical_Footprint_File: http://fcl.am.freescale.net/ALLEGRO/step/con_skt1x8_th.STEP; AGILE_PN: 210-81510; CAD_APPROVED: Yes; HEIGHT: 8.636; MFG_NAME01: SAMTEC; MFG_PN01: SSQ-108-01-F-S; ROHS: Yes; Temp Range: -55C to +125C
J13 = CONN_HDR_10X1: CON 1X10 SKT TH 100MIL SP 340H AU 104L; 3D_Mechanical_Footprint_File: http://fcl.am.freescale.net/ALLEGRO/step/con_skt1x10_th_104l.STEP; AGILE_PN: 210-81512; CAD_APPROVED: Yes; FPLIST: con_skt1x10_th_104l,con_skt1x10_th; HEIGHT: 8.636; MFG_NAME01: SAMTEC; MFG_PN01: SSQ-110-01-F-S; ROHS: Yes; Temp Range: -55C to +125C
J27 = CONN_HDR_10X2: HDR 2X10 TH 100MIL CTR 338H AU 100L; 3D_Mechanical_Footprint_File: ftp://fcl.am.freescale.et/ALLEGRO/step/hdr210.step; AGILE_PN: 210-81083; CAD_APPROVED: Yes; HEIGHT: 8.59; JUMPER (DEFAULT): 1-2,3-4,5-6,7-8,11-12,13-14,15-16,17-18,19-20; MFG_NAME01: SAMTEC; ROHS: Yes; Temp Range: -55°C to +125°C
J28 = CONN_HDR_5X2: HDR 2X5 SMT 50MIL CTR 246H AU; 3D_Mechanical_Footprint_File: http://fcl.am.freescale.net/ALLEGRO/step/hdr205_10m_50_sm_k.STEP; AGILE_PN: 211-79478; ASSY_NOTE: CUT PIN 7; CAD_APPROVED: Yes; HEIGHT: 6.25; MFG_NAME01: SAMTEC; ROHS: Yes; SILK: NFC-DEBUG
R7 R8 = 3_Pad_Solder_Blob_Jumper_short: SOLDER BLOB JUMPER 3PIN 1-2 SHORT 0603 - NO PART TO ORDER; AGILE_PN: 470-83437; CAD_APPROVED: Yes; HEIGHT: 0.1016; ROHS: Yes; SHORT (DEFAULT): 1-2; SILK: HOST_SEL0
R15 = 3_Pad_Solder_Blob_Jumper: SOLDER BLOB JUMPER 3PIN OPEN 0603 - NO PART TO ORDER; AGILE_PN: 470-81222; CAD_APPROVED: Yes; FPLIST: 3pin_0603_solder_blob_jumper,3pin_0603_solder_blob_jumper_nsp; HEIGHT: 0.1016; MFG_NAME01: NO PART TO ORDER; MFG_PN01: N/A (CUSTOM PCB CONNECTION); ROHS: Yes; SHORT (DEFAULT): OPEN; SILK: VEN
R16 = 3_Pad_Solder_Blob_Jumper_short: SOLDER BLOB JUMPER 3PIN 1-2 SHORT 0603 - NO PART TO ORDER; AGILE_PN: 470-83437; CAD_APPROVED: Yes; HEIGHT: 0.1016; ROHS: Yes; SHORT (DEFAULT): 1-2; SILK: MODE_SWITCH
R56 R64 R67 R71 = RES: RES MF 10K 1/16W 1% 0402; AGILE_PN: 470-80452; CAD_APPROVED: Yes; FPLIST: RC0402_25,RC0402_HD,0402_CC,RC0402_X2; HEIGHT: 0.40; MFG_NAME01: VISHAY; MFG_PN01: CRCW040210K0FKEDC; ROHS: Yes; Tolerance: 1%
R60 R68 = RES: RES MF 1.0K 1/16W 5% 0402; AGILE_PN: 470-82125; CAD_APPROVED: Yes; FPLIST: RC0402_25,RC0402_HD,RC0402_X2,0402_CC; HEIGHT: 0.4; MFG_NAME01: NIC COMPONENTS CORP; MFG_PN01: NRCL04J102TRF; ROHS: Yes; Temp Range: -55°C to +155°C; Temp_Range: -55°C to +155°C; Tolerance: 5%
R62 R76 R77 R165 = RES: RES MF 1.5K 1/8W 1% 0805; AGILE_PN: 470-75955; CAD_APPROVED: Yes; FPLIST: RC0805_OV,RC0805,0805_CC; HEIGHT: 0.70; MFG_NAME01: BOURNS; MFG_PN01: CR0805-FX-1501ELF; ROHS: Yes; Temp Range: –55 °C to +155 °C; Tolerance: 1%
R69 R173 = RES: RES MF 2.2K 1/16W 1% 0402; AGILE_PN: 470-78359; CAD_APPROVED: Yes; FPLIST: RC0402_25,RC0402_HD,0402_CC; HEIGHT: 0.4; MFG_NAME01: NIC COMPONENTS CORP; MFG_PN01: NRCL04F2201TRF; ROHS: Yes; Temp Range: -55C to +155C; Temp_Range: -55C to +155C; Tolerance: 1%
R90 R91 = RES: RES MF 2.2K 1/16W 1% 0402; AGILE_PN: 470-78359; ASSY_OPT: DNP; CAD_APPROVED: Yes; FPLIST: RC0402_25,RC0402_HD,0402_CC; HEIGHT: 0.4; MFG_NAME01: NIC COMPONENTS CORP; MFG_PN01: NRCL04F2201TRF; ROHS: Yes; Temp Range: -55C to +155C; Temp_Range: -55C to +155C; Tolerance: 1%
SJ3 SJ4 SJ7-SJ10 = 2_Pad_Solder_Blob_Jumper: SOLDER BLOB JUMPER 0402 SHORT NO PART TO ORDER; AGILE_PN: 470-81066; CAD_APPROVED: Yes; HEIGHT: 0.1; MFG_NAME01: NA; MFG_PN01: NO PART TO ORDER1; ROHS: Yes
SJ11 = 2-PIN_PAD: JUMPER 2 PAD 0805 SMT, NO PART TO ORDER; AGILE_PN: 211-79320; CAD_APPROVED: Yes; HEIGHT: 0.1; MFG_NAME01: NA; MFG_PN01: NO PART TO ORDER1; ROHS: Yes
TP15-TP20 TP24-TP28 TP32 TP33 TP39 TP43 TP50 TP52 = TESTLOOP: TEST POINT PAD 40MIL DIA SMT, NO PART TO ORDER; AGILE_PN: 211-76643; CAD_APPROVED: Yes; HEIGHT: 0.1; MFG_NAME01: NOTACOMPONENT; MFG_PN01: NOTACOMPONENT; ROHS: Yes
C92 C93 = CAP_NP: CAP CER 68pF 250V 1% C0G 0805; AGILE_PN: 150-79296; ASSY_OPT: DNP; CAD_APPROVED: Yes; FPLIST: CC0805_OV,CC0805,0805_CC; HEIGHT: 1.44; MFG_NAME01: AMERICAN TECHNICAL CERAMICS CORP; MFG_PN01: 600F680FT250XT; Package Size: 0805; Package Type: Tape & reel; ROHS: Yes; Rated Voltage: 250V; Temp Range: -55C to +125C; Tolerance: 1%; VOLTAGE: 250V
C95 C96 = CAP_NP: CAP CER 68pF 250V 1% C0G 0805; AGILE_PN: 150-79296; CAD_APPROVED: Yes; FPLIST: CC0805_OV,CC0805,0805_CC; HEIGHT: 1.44; MFG_NAME01: AMERICAN TECHNICAL CERAMICS CORP; MFG_PN01: 600F680FT250XT; Package Size: 0805; Package Type: Tape & reel; ROHS: Yes; Rated Voltage: 250V; Temp Range: -55C to +125C; Tolerance: 1%; VOLTAGE: 250V
C97 C103 = CAP_NP: CAP CER 18pF 250V 1% C0G 0805; AGILE_PN: 150-79275; CAD_APPROVED: Yes; FPLIST: CC0805_OV,CC0805,0805_CC; HEIGHT: 1.44; MFG_NAME01: AMERICAN TECHNICAL CERAMICS CORP; MFG_PN01: 600F180FT250XT; Package Size: 0805; Package Type: Tape & reel; ROHS: Yes; Rated Voltage: 250V; Temp Range: -55C to +125C; Tolerance: 1%; VOLTAGE: 250V
C98 C100 = CAP_NP: CAP CER 100pF 250V 1% C0G 0805; AGILE_PN: 150-79292; CAD_APPROVED: Yes; FPLIST: CC0805_OV,CC0805,0805_CC; HEIGHT: 1.44; MFG_NAME01: AMERICAN TECHNICAL CERAMICS CORP; MFG_PN01: 600F101FT250XT; Package Size: 0805; ROHS: Yes; Rated Voltage: 250V; Temp Range: -55C to +125C; Tolerance: 1%; VOLTAGE: 250V
C101 C105 = CAP_NP: CAP CER 47pF 250V 1% C0G 0805; AGILE_PN: 150-79301; CAD_APPROVED: Yes; FPLIST: CC0805_OV,CC0805,0805_CC; HEIGHT: 1.44; MFG_NAME01: AMERICAN TECHNICAL CERAMICS CORP; MFG_PN01: 600F470FT250XT; Package Size: 0805; Package Type: Tape & reel; ROHS: Yes; Rated Voltage: 250V; Temp Range: -55C to +125C; Tolerance: 1%; VOLTAGE: 250V
C102 C104 = CAP_NP: CAP CER 180pF 50V 1% C0G 0402; AGILE_PN: 150-80736; CAD_APPROVED: Yes; FPLIST: CC0402_25,CC0402_HD,0402_CC; HEIGHT: 0.56; MFG_NAME01: AVX; MFG_PN01: 04025A181FAT2A; Package Size: 0402; ROHS: Yes; Rated Voltage: 50V; Temp Range: -55C to +125C; Temp_Range: -55C to +125C; Tolerance: 1%
J29 J30 = CONN_HDR_4X1: CON 1X4 SKT TH 100MIL SP 340H AU 104L; 3D_Mechanical_Footprint_File: http://fcl.am.freescale.net/ALLEGRO/step/con_skt1x4_th.STEP; AGILE_PN: 210-80462; ASSY_OPT: DNP; CAD_APPROVED: Yes; HEIGHT: 8.64; MFG_NAME01: SAMTEC; MFG_PN01: SSW-104-01-G-S; ROHS: Yes; Temp Range: -55°C to +125°C
J31 J32 = CONN_HDR_7X1: CON 1X7 SKT TH 100MIL SP 340H AU 104L; 3D_Mechanical_Footprint_File: http://fcl.am.freescale.net/ALLEGRO/step/con_1x7_skt_2p54_th.STEP; AGILE_PN: 210-81383; ASSY_OPT: DNP; CAD_APPROVED: Yes; HEIGHT: 8.636; MFG_NAME01: SAMTEC; MFG_PN01: SSW-107-01-G-S; ROHS: Yes; Temp Range: -55C to +125C; Temp_Range: -55C to +125C
J33 = CONN_HDR_1X1_TH: HDR 1X1 TH -- 338H AU 100L; 3D_Mechanical_Footprint_File: http://fcl.am.freescale.net/ALLEGRO/step/hdr_1x1.STEP; AGILE_PN: 210-79790; ASSY_OPT: DNP; CAD_APPROVED: Yes; HEIGHT: 8.89; MFG_NAME01: SAMTEC; MFG_PN01: TSW-101-07-L-S; ROHS: Yes; Temp Range: -55°C to +125°C
P1 = TP_RECT_56P_EP: NFC MODULE 4X14 23X23MM NO PART TO ORDER; AGILE_PN: 510-78458; CAD_APPROVED: Yes; HEIGHT: 2.35; ROHS: Yes
R73 R74 R79 R80 = RES: RES MF 2.2 OHM 1/3W 1% 0805; AGILE_PN: 470-82358; CAD_APPROVED: Yes; FPLIST: RC0805_OV,RC0805,0805_CC; HEIGHT: 0.5; MFG_NAME01: SUSUMU CO. LTD.; MFG_PN01: RL1220S-2R2-F; ROHS: Yes; Temp Range: -55°C to +125°C; Tolerance: 1%
R75 R81 = RES: RES MF ZERO OHM 1/8W -- 0805; AGILE_PN: 470-75442; ASSY_OPT: DNP; CAD_APPROVED: Yes; FPLIST: RC0805_OV,RC0805,RC0805_OV_3P,0805_CC; HEIGHT: 0.7; MFG_NAME01: YAGEO AMERICA; MFG_PN01: RC0805JR-070RL; ROHS: Yes; Temp Range: –55 °C to +155 °C; Tolerance: 5%
C134 = CAP_NP: CAP CER 0.1UF 16V 10% X5R 0402; AGILE_PN: 150-75663; CAD_APPROVED: Yes; FPLIST: CC0402_25,CC0402_HD,0402_CC,CC0402_18,capc0402_l; HEIGHT: 1; MFG_NAME01: MURATA; MFG_PN01: GRM155R61C104KA88D; Package Size: 1x0.5MM; Package Type: SMT; ROHS: NULL; Rated Voltage: 16V; TOL: 10%; Temp Range: -55C to +85C; Tolerance: 10%; VOLTAGE: 16V
D16 = LED: LED ULTRA-BRIGHT YELLOW 30MA 5V SMT 0603; AGILE_PN: 370-75076; CAD_APPROVED: Yes; HEIGHT: 0.8; MFG_NAME01: LITE ON; MFG_PN01: LTST-C190KSKT; SILK: NFC
D17 = LED: LED GRN SGL 25MA 0603; AGILE_PN: 370-76549; CAD_APPROVED: Yes; HEIGHT: 0.85; MFG_NAME01: KINGBRIGHT; MFG_PN01: KPT-1608SGC; SILK: EMVCO
D18 = LED: LED BLUE -- 20MA SMT; AGILE_PN: 370-75078; CAD_APPROVED: Yes; HEIGHT: 0.8; MFG_NAME01: LITE ON; MFG_PN01: LTST-C190TBKT; ROHS: Yes; Rated Voltage: 3V; SILK: VEN; VOLTAGE: 3V
D19 = LED: LED ULTRA BRIGHT ORANGE 20MA 2V SMT 0603; AGILE_PN: 370-75080; CAD_APPROVED: Yes; HEIGHT: 0.8; MFG_NAME01: LITE ON; MFG_PN01: LTST-C190KFKT; ROHS: Yes; SILK: DC5V
J43 = CONN_RCPT_2X20: CON 2X20 SKT TH 100MIL CTR 335H SN 104L; 3D_Mechanical_Footprint_File: http://fcl.am.freescale.net/PDF_3D_STEP/con_skt2x20_th.step; AGILE_PN: 210-75952; CAD_APPROVED: Yes; HEIGHT: 8.51; MFG_NAME01: SAMTEC; MFG_PN01: SSW-120-01-T-D; Package Size: 4.95X51.31MM; ROHS: Yes

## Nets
1V8_VDD: C28.1 C30.1 C37.1 R1.1 R2.3 U7.2(OUT) U7.4(TAB)
3V3_5V0: C15.1 C20.1 C32.1 J1.1 J2.1 J4.1 R28.1 TP7.1(Pin1) U5.4(OUT)
3V3_VDD: C9.1 C29.1 C34.1 J12.4 R2.2 R20.1 R164.1 R165.1 R172.1 R173.1 U6.2(VOUT) U6.4(TAB) ; also on sheet 2
GND: C1.2 C2.2 C3.2 C4.2 C5.2 C7.2 C9.2 C10.2 C11.2 C14.2 C15.2 C16.2 C17.2 C19.2 C23.2 C24.2 C25.2 C26.2 C28.2 C29.2 C30.2 C31.2 C32.2 C33.2 C34.2 C35.2 C37.2 C38.2 C63.2 C64.2 C65.2 C66.2 C67.2 C68.2 C69.2 C91.2 C92.2 C93.1 C95.1 C96.2 C98.1 C100.2 C102.2 C104.2 C134.2 D4.A D5.A J6.A1(GND1) J6.A12(GND2) J6.B1(GND3) J6.B12(GND4) J7.A1(GND1) J7.A12(GND2) J7.B1(GND3) J7.B12(GND4) J8.1 J8.2 J9.1 J9.2 J12.6 J12.7 J13.4 J27.9 J27.10 J28.3(A2) J28.5(A3) J31.4 J32.4 J43.39 L7.2 L9.2 P1.2 P1.5 P1.7 P1.9 P1.12 P1.17 P1.23 P1.38 P1.45 P1.48 P1.50 P1.53 P1.57(EPAD) Q1.2(SOURCE) Q2.2(SOURCE) Q3.2(SOURCE) Q4.2(SOURCE) Q5.2(SOURCE) Q6.2(SOURCE) Q7.2(SOURCE) R3.1 R5.2 R6.2 R7.3 R10.2 R11.2 R13.2 R18.2 R64.2 R85.2 R86.2 R89.1 SJ11.1 TP1.1(Pin1) TP5.1(Pin1) U2.B1(GND) U5.3(GND) U5.6(TAB) U6.1(GND) ; also on sheet 1 2
VBAT: C10.1 C25.1 C35.1 J4.2 P1.49 R26.1
VBATPWR: C3.1 C23.1 P1.46 R17.2
VBUS_DC: D5.C J7.A4(VBUS1) J7.A9(VBUS2) J7.B4(VBUS3) J7.B9(VBUS4) L8.2
VBUS_PA: D4.C J6.A4(VBUS1) J6.A9(VBUS2) J6.B4(VBUS3) J6.B9(VBUS4) L6.2
VDDIO: C16.1 C19.1 P1.44 SH1.2
VDDIO_BRD: J12.2 J28.1(A1) Q1.1(GATE) R2.1 R7.2 R56.2 R62.1 R67.2 R68.1 R69.1 R71.2 R90.1 R91.1 SH1.1 TP6.1(Pin1) ; also on sheet 1 2
VDDPA: P1.52 R26.2
ANT_1: J29.2 J29.3 J30.2 J30.3 R73.2 R74.2 R79.2 R80.2
C_TX1: C95.2 C97.2 C98.2 C105.2 R74.1 R75.2 R79.1
C_TX2: C96.1 C100.1 C101.2 C103.2 R73.1 R80.1 R81.2
DC5V: C134.1 J5.3(A2) J43.2 J43.4 SJ10.1
EXT_MODE_SWITCH_SP: J27.6 R144.2
EXT_MODE_SWITCH_SP_DONE: J27.8 R122.1
GREEN_LED: J43.19 R15.2 SJ8.1
J_VBATPWR: C7.1 C26.1 J2.2 R17.1
J_VUP: C5.1 C11.1 J1.2 R23.1
JTAG_TDO: J28.6(B3) R56.1
JTAG_TMS_SWDIO: J28.2(B1) P1.25 R67.1
K82_MODE_SWITCH_SP: J27.5 ; also on sheet 2
K82_MODE_SWITCH_SP_DONE: J27.7 ; also on sheet 2
K82_NFC_IRQ: J27.19 ; also on sheet 2
K82_PTA20: J27.1 ; also on sheet 2
K82_PTA21: J27.3 ; also on sheet 2
K82_SPI1_CLK: J27.13 ; also on sheet 2
K82_SPI1_CS0: J27.15 ; also on sheet 2
K82_SPI1_MISO: J27.11 ; also on sheet 2
K82_SPI1_MOSI: J27.17 ; also on sheet 2
LP3856_ADJ_R: C20.2 J3.1 R5.1 R28.2 U5.5(ADJ)
NFC_AUX1: J10.3 P1.18
NFC_AUX2: J10.2 P1.19
NFC_CLK: P1.22 TP33.1(Pin1)
NFC_CLK_AUX: J15.5 P1.56 TP50.1(Pin1)
NFC_DWL_REQ: J14.1 P1.27
NFC_GPIO0: J13.9 P1.28 TP19.1(Pin1)
NFC_GPIO1: J13.10 P1.31 TP18.1(Pin1)
NFC_GPIO3: P1.30 R8.1
NFC_GPIO4: J14.2 P1.32 TP16.1(Pin1)
NFC_GPIO5: J13.2 P1.33 TP17.1(Pin1)
NFC_GPIO6: J13.6 P1.16 TP25.1(Pin1)
NFC_GPIO7: J13.7 P1.13 TP26.1(Pin1)
NFC_GPIO8: J13.5 P1.14 TP27.1(Pin1)
NFC_GPIO9: J13.8 P1.15 TP28.1(Pin1)
NFC_HOST_SEL0: P1.20 R7.1
NFC_HOST_SEL1: P1.21 R89.2
NFC_I2C_IRQ: P1.3 R152.2 TP15.1(Pin1)
NFC_I2C_SCL: P1.40 R90.2 R127.2
NFC_I2C_SDA: P1.39 R8.2 R91.2 R137.2
NFC_INT_AUX: J15.4 P1.54 TP43.1(Pin1)
NFC_IO_AUX: J15.3 P1.55 TP39.1(Pin1)
NFC_IRQ: J27.20 P1.26 SJ4.1
NFC_JTAG_RST: D12.1(A1) D12.2(A2) R60.2 TP24.1(Pin1)
NFC_MODE_SWITCH: P1.29 R16.2 R141.1 SJ3.1
NFC_RXN: J31.6 J32.6 P1.4 R75.1 R76.2
NFC_RXP: J31.2 J32.2 P1.10 R77.1 R81.1
NFC_SPI_CLK: J27.14 P1.35
NFC_SPI_MISO: J27.12 P1.34
NFC_SPI_MOSI: J27.18 P1.37
NFC_SPI_NSS: J27.16 P1.36
NFC_TX1: C93.2 C97.1 C102.1 C105.1 J31.5 J32.5 P1.6 R76.1
NFC_TX2: C92.1 C101.1 C103.1 C104.1 J31.3 J32.3 P1.8 R77.2
NFC_VEN: P1.43 R15.3 R142.1 SJ9.1
nRESET: D12.3(C) J28.10(B5)
PU-R_RST_B: C91.1 R60.1 R68.2
PWR_ON: D1.A(ANODE) R20.2
R_5V0_ADJ: J3.2 R6.1
SDB: R21.2 U5.1(~{SHDN})
USB0_RDN: R25.1 ; also on sheet 2
USB0_RDP: R27.1 ; also on sheet 2
USB_5V_DC: C66.1 C67.1 C68.1 C69.1 J5.5(A3) L8.1 TP3.1(Pin1) ; also on sheet 2
USB_5V_PA: C24.1 C63.1 C64.1 C65.1 J5.1(A1) L6.1 TP2.1(Pin1)
USB_CC1_DC: J7.A5(CC1) R11.1 TP10.1(Pin1)
USB_CC1_PA: J6.A5(CC1) R86.1 TP8.1(Pin1)
USB_CC2_DC: J7.B5(CC2) R10.1 TP11.1(Pin1)
USB_CC2_PA: J6.B5(CC2) R85.1 TP9.1(Pin1)
USB_DC_SHLD: J7.SH1 J7.SH2 J7.SH3 J7.SH4 L9.1
USB_DN: J7.A7(D-_1) J7.B7(D-_2) U2.A2(CH1_IN-)
USB_DP: J7.A6(D+_1) J7.B6(D+_2) U2.A1(CH1_IN+)
USB_PA_SHLD: J6.SH1 J6.SH2 J6.SH3 J6.SH4 L7.1
VMAIN: C1.1 C2.1 C14.1 C17.1 C33.1 C38.1 J5.2(B1) J5.4(B2) J5.6(B3) J12.5 R21.1 U5.2(IN) U6.3(VIN) U7.3(IN)
VUP: C4.1 C31.1 J33.1 P1.51 R23.2
YELLOW_LED: J43.23 R16.3 SJ7.1
N27599440: J29.1 J30.1
N27599525: J29.4 J30.4
N27867846: P1.11 TP52.1(Pin1)
N27989341: D1.C(CATHODE) Q1.3(DRAIN)
N27993186: P1.41 TP20.1(Pin1)
N27993212: P1.42 TP32.1(Pin1)
N28179141: J28.8(B4) R71.1
N28179177: J28.4(B2) P1.24 R64.1
N28179212: J28.9(A5) SJ11.2
N28179372: D11.A(ANODE) R62.2
N28179376: D15.A(ANODE) R69.2
N28179481: D11.C(CATHODE) Q6.3(DRAIN)
N28179485: D15.C(CATHODE) Q7.3(DRAIN)
N28319858: R1.2 R4.1 R14.1 U7.1(ADJ)
N28319891: R3.2 R4.2
N28319921: R3.3 R14.2
N28331755: D16.A(ANODE) R164.2
N28331792: D16.C(CATHODE) Q4.3(DRAIN)
N28331794: D17.A(ANODE) R165.2
N28331876: Q4.1(GATE) SJ7.2
N28331878: D18.A(ANODE) R172.2
N28331886: D17.C(CATHODE) Q5.3(DRAIN)
N28332010: D18.C(CATHODE) Q2.3(DRAIN)
N28332022: Q5.1(GATE) SJ8.2
N28332036: D19.A(ANODE) R173.2
N28332155: J43.5 R127.1
N28332189: J43.3 R137.1
N28332225: J43.40 R142.2
N28332293: D19.C(CATHODE) Q3.3(DRAIN)
N28332350: J43.38 R141.2
N28421669: Q2.1(GATE) SJ9.2
N28421722: Q3.1(GATE) SJ10.2
N28430174: J10.1 R8.3
N28430681: Q6.1(GATE) SJ3.2
N28430684: Q7.1(GATE) SJ4.2
N28503659: J27.4 R16.1
N28503664: J27.2 R15.1
N28509733: J43.24 R122.2
N28509890: J43.21 R144.1
N28651788: J43.37 R152.1
N28673617: R12.1 U2.C1(CH1_OUT+)
N28673619: R12.2 R13.1 R27.2
N28673663: R19.1 U2.C2(CH1_OUT-)
N28673665: R18.1 R19.2 R25.2

Not connected (* = marked no-connect by the designer): J6 A2(TX1+)* A3(TX1-)* A6(D+_1) A7(D-_1) A8(SBU1)* A10(RX2-)* A11(RX2+)* B2(TX2+)* B3(TX2-)* B6(D+_2) B7(D-_2) B8(SBU2)* B10(RX1-)* B11(RX1+)*; J7 A2(TX1+)* A3(TX1-)* A8(SBU1)* A10(RX2-)* A11(RX2+)* B2(TX2+)* B3(TX2-)* B8(SBU2)* B10(RX1-)* B11(RX1+)*; J12 1 3 8; J13 1 3; J14 3 4 5 6 7 8; J15 1 2 6 7 8; J28 7(A4)*; J31 1* 7*; J32 1* 7*; J43 1 6 7 8 9 10 11 12 13 14 15 16 17 18 20 22 25 26 27 28 29 30 31 32 33 34 35 36; P1 1* 47*

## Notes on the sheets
sheet 5
- POWER SECTION
- NO USB_VBUS
- NO AD1
- USB TYPE C for Power Adapter
- i
- Jumper J1 Settings
  ===============
  Open for default operation (DC/DC supplies VUP)
  1-2 for ULPCD operation (DC/DC must be disabled in PN7220 settings!)
- i
- Layout Note: Filter (VUP/VBAT/VBATPWR)
  ===================================
  Place Filter section & Decaps as close as possible to the Module
- VUP
  (3.3/4.77V)
- i
- i
- Jumper J5 Settings
  ==============
  1-2: USB ADAPTER POWER INPUT (default)
  3-4: DRAGON BOARD PWR
  5-6: USB DEVICE POWER INPUT
- Note:USB_CC monitor
  ==================
  default (2.0:500mA, 3.1:900mA): <0.66V
  1.5A: >0.66V & <1.23V
  3A: >1.23V
- LDO 3V3 (4.77V Optional) , 0.8A(presumptive max)
- VBATPWR
  (3.3/4.77V)
- Cff
- PN7220 SOCKET INTERFACE
- R1
- i
- VBAT
  (3.3/4.77V)
- Layout Note: U5
  ==============
  Provide GND Copper PAD 1.0 square inch
  on Top & Bottom for thermal (centered to TAB),
  Add multiple Vias for thermal transfer
- R2
- i
- Jumper J3 Settings
  ===============
  Open: 3V3 (Default)
  Close: 4.77V
- PNEV7220MB INTERFACE
- USB TYPE C for Device Communication
- VDDPA
  (3.3/4.77V)
- LDO 1.8V (1.9V Optional), 0.8A (presumptive max)
- VDDIO
  (3.3/1.8V)
- i
- Layout Note:
  ==========
  Maintain 90 ohm differential impedance
- i
- Layout Note:
  ==========
  Place ESD and EMI filter close to USB Connector
- i
- Layout Note: U7
  ===============
  Place Decaps as close as possible to the LDO
- 1.8V/1.9V
- i
- Solder Jumper R3 Settings
  =====================
  1&2 -> 1.8V = 1.25 x (1 + 80.6/180)
  1&3 -> 1.9V = 1.25 x (1 + 95.3/180)
- GND
- i
- i
- Note:USB_CC monitor
  ==================
  default (2.0:500mA, 3.1:900mA): <0.66V
  1.5A: >0.66V & <1.23V
  3A: >1.23V
- GND
- GND
- 3.3V
- LDO 3.3V, 0.8A (presumptive max)
- THERMAL PAD
  FOR MODULE
- i
- Layout Note: U6
  ===============
  Place Decaps as close as possible to the LDO
- GROUND POINTS
- Layout Note:
  Place close to Module
- Layout Note:
  Place at board edge
sheet 6
- PNEV7220MB INTERFACE
- I2C_SCL
- I2C3_SCL_3V3
- CONTACT INTERFACE
- GND
- TDA_CMDVCC_B
- I2C3_SDA_3V3
- I2C_SDA
- TDA_EN5V_3VN
- TDA_CLKDIV1
- TDA_CLKDIV2
- TDA_EN1V8
- HOST_SEL0
- IO_AUX
- PNEV7220MB INTERFACE
- HOST_SEL1
- TDA_RSTIN
- INT_AUX
- PRD1
- CLK_AUX
- PRD2
- GND
- IRQ
- VEN
- SAI5_RXC
- GPIO4
- DWL_REQ
- GPIO5
- CLK
- NFCC HOST INTERFACE
- GPIO6/SPIM_MISO
- GND
- GPIO7/SPIM_MOSI
- ATX_A/SPI_MISO
- GPIO8/SPIM_SCLK
- ATX_B/SPI_SCK
- GPIO9/SPIM_SSN
- ATX_C/SPI_NSS
- ATX_D/SPI_MOSI
- K82 ( From Int. MCU)
- EXTERNAL ( From Ext. MCU)
- i
- Jumper J27 Settings
  ================
  1-2, 3-4, 5-6, 7-8 (close): K82 <--> IMX8 (default)
  1, 3, 5, 7 (open): K82 <--> EXT HOST MCU
  2, 4, 6, 8 (open): EXT SECURE MCU <--> IMX8
  9, 10 (open): COMMON GND
  11-12, 13-14, 15-16, 17-18, 19-20 (close): K82 <--> INT PN7220 (default)
  11, 13, 15, 17, 19 (open): K82 <--> EXT PN7220
  12, 14, 16, 18, 20 (open): EXT SECURE MCU <--> INT PN7220
- GND
- GPIO1
- GPIO3
- GPIO2
- SAI5_RXD0
- SWD NFCC
- GPIO0
- LPC-Link2: Pinout
- Note:
  JTAG for external
  JLINK default
- SWDIO
- info:
  cut/remove pin 7
- JTAG_TCK/SWDCLK
- JTAG_TDI
- SWDCLK
- GND
- SILK = AUX2
- SILK = GPIO3
- AUX2
- SILK = AUX1
- AUX1
- AUX3
- SAI5_RXD1
- GND
sheet 7
- NFC ANTENNA INTERFACE
- VTUNE1
- ANTENNA MATCHING
- PCB ANTENNA 45 x 45 mm
- RXP
- 45mm x 45mm
- GND
- 100mil pitch
- TX2
- GND
- TX1
- GND
- RXN
- LAYOUT ANTENNA
- i
- Layout Note: (RF Critical)
  =========
  Reuse 45mm x45mm Antenna.Zip Layout received from
   BLR Team for placement, Routing. Should reproduce the Original design without Mismatch
- i
- Layout Note:
  =========
  Refer/Reuse PNEV5180B's Layout for placement, Routing
- PNEV7220MB INTERFACE
sheet 8
- STATUS LEDS
- iMX8 EVK (NANO/MINI) Interface
- I2C3_SDA_3V3
- I2C3_SCL_3V3
